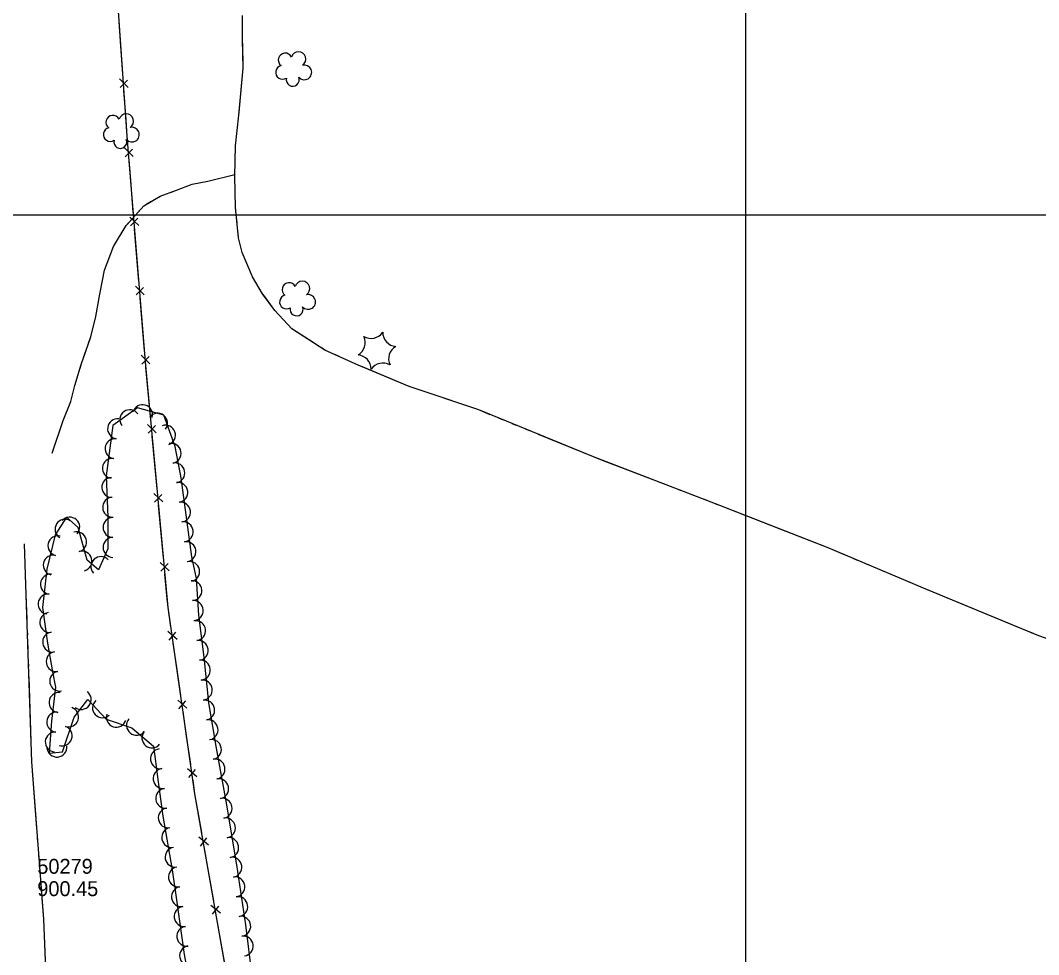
# Model space of a CAD drawing. Extents: x 353423 to 364002, y 127000 to 201942.
# Drawn here: x 361707.9 to 362117.9, y 131702.2 to 132078.2 of the extents above; entities that cross this region are included whole.
import ezdxf

# ---------------------------------------------------------------- set-up
doc = ezdxf.new("R2010")
doc.units = 0
for name, color, linetype in [('E_DTM_SlopeBottom', 7, 'Continuous'), ('E_FEN_Generic', 7, 'Continuous'), ('E_LAND_TreeLine', 7, 'Continuous'), ('E_RDWY_AsphConc', 7, 'Continuous'), ('E_STRUCT_WingWall', 7, 'Continuous')]:
    doc.layers.add(name, color=color, linetype=linetype)

msp = doc.modelspace()

# ---------------------------------------------------------------- linework, layer by layer
at = {"layer": 'E_DTM_SlopeBottom'}
for p, q in [((361751.3, 132051.27), (361747.8, 132054.76)), ((361748.05, 132051.22), (361751.02, 132054.23)), ((361753.32, 132023.46), (361749.79, 132026.91)), ((361750.08, 132023.37), (361753.02, 132026.42)), ((361755.58, 131995.64), (361752.04, 131999.09)), ((361752.33, 131995.55), (361755.27, 131998.6)), ((361757.83, 131967.83), (361754.3, 131971.28)), ((361754.58, 131967.74), (361757.52, 131970.78)), ((361760.08, 131940.01), (361756.55, 131943.46)), ((361756.84, 131939.92), (361759.78, 131942.97)), ((361762.66, 131912.24), (361759.08, 131915.65)), ((361759.41, 131912.11), (361762.32, 131915.2)), ((361765.22, 131884.45), (361761.65, 131887.86)), ((361761.97, 131884.33), (361764.88, 131887.41)), ((361767.78, 131856.67), (361764.21, 131860.08)), ((361764.54, 131856.54), (361767.44, 131859.62)), ((361771.02, 131829.05), (361767.27, 131832.27)), ((361767.78, 131828.75), (361770.52, 131831.98)), ((361775.01, 131801.43), (361771.26, 131804.65)), ((361771.77, 131801.13), (361774.51, 131804.36)), ((361779, 131773.81), (361775.25, 131777.03)), ((361775.76, 131773.51), (361778.5, 131776.74)), ((361783.62, 131746.34), (361779.78, 131749.45)), ((361780.4, 131745.95), (361783.04, 131749.26)), ((361788.47, 131718.86), (361784.63, 131721.96)), ((361785.24, 131718.46), (361787.88, 131721.77))]:
    msp.add_line(p, q, dxfattribs=at)
for points in [[(361878.29, 131213.33), (361848.45, 131372.9), (361823.99, 131512.17), (361810.41, 131584.23), (361778.23, 131766.92), (361767.39, 131841.96), (361758.28, 131940.75), (361750.91, 132031.6), (361745.14, 132114.91), (361734.25, 132261.02), (361730.83, 132314.1), (361722.15, 132402.74), (361735.2, 132462.79), (361756.62, 132560.57), (361777.4, 132659.3), (361799.83, 132762.09), (361820.91, 132859.48), (361836.68, 132931.42), (361851.79, 133001.8)], [(361748.4, 132067.88), (361747.71, 132077.83)], [(361749.18, 132056.57), (361748.4, 132067.88)], [(361750.33, 132040.04), (361749.64, 132049.99)], [(361751.15, 132028.73), (361750.91, 132031.6), (361750.33, 132040.04)], [(361752.49, 132012.22), (361751.68, 132022.16)], [(361753.4, 132000.92), (361752.49, 132012.22)], [(361754.74, 131984.4), (361753.93, 131994.34)], [(361755.66, 131973.1), (361754.74, 131984.4)], [(361756.99, 131956.59), (361756.19, 131966.53)], [(361757.91, 131945.29), (361756.99, 131956.59)], [(361759.38, 131928.78), (361758.47, 131938.71)], [(361760.42, 131917.49), (361759.38, 131928.78)], [(361761.94, 131900.99), (361761.03, 131910.93)], [(361762.98, 131889.7), (361761.94, 131900.99)], [(361764.51, 131873.21), (361763.59, 131883.14)], [(361765.55, 131861.91), (361764.51, 131873.21)], [(361767.07, 131845.42), (361766.15, 131855.35)], [(361768.51, 131834.17), (361767.39, 131841.96), (361767.07, 131845.42)], [(361770.88, 131817.78), (361769.46, 131827.65)], [(361772.51, 131806.55), (361770.88, 131817.78)], [(361774.87, 131790.16), (361773.45, 131800.03)], [(361776.5, 131778.93), (361774.87, 131790.16)], [(361779, 131762.56), (361778.23, 131766.92), (361777.44, 131772.41)], [(361780.97, 131751.39), (361779, 131762.56)], [(361783.84, 131735.07), (361782.11, 131744.9)], [(361785.81, 131723.91), (361783.84, 131735.07)], [(361788.68, 131707.59), (361786.95, 131717.41)], [(361790.65, 131696.42), (361788.68, 131707.59)]]:
    msp.add_lwpolyline(points, dxfattribs=at)
at = {"layer": 'E_FEN_Generic'}
msp.add_lwpolyline([(361801.32, 131693.58), (361798.69, 131714.25), (361795.08, 131738.38), (361790.81, 131764), (361786.89, 131785.27), (361783.78, 131803.52), (361781.99, 131822.01), (361779.78, 131838.92), (361778.8, 131853.62), (361777.01, 131862.31), (361772.64, 131894.17), (361770.24, 131906.73), (361765.7, 131919.32), (361755.11, 131922.31), (361745.13, 131915.21), (361742.44, 131894.89), (361743.14, 131878.24), (361743.11, 131865.58), (361739.45, 131857.09), (361734.77, 131861.05), (361731.16, 131874.14), (361726.45, 131878.26), (361721.96, 131871.15), (361718.6, 131857.31), (361716.78, 131841.89), (361718.86, 131827.57), (361720.92, 131816.11), (361722.08, 131809.89), (361720.46, 131796.22), (361719.53, 131783.3), (361724.84, 131783.88), (361729.53, 131797.8), (361735.06, 131804.86), (361742.41, 131796.96), (361752.74, 131793.45), (361761.55, 131786.17), (361763.33, 131772.74), (361765.22, 131757.98), (361769.01, 131736.32), (361770.84, 131724.31), (361773.81, 131702.33), (361778.15, 131679.04)], dxfattribs=at)
for centre, radius, start, end in [((361819.91, 132062.67), 2.97, 302.955, 164.1889), ((361814.55, 132062.27), 2.78, 25.9259, 233.6989), ((361813.51, 132057.31), 2.78, 102.6029, 303.614), ((361822.24, 132057.3), 2.97, 220.6058, 103.5791), ((361817.58, 132054.33), 2.61, 165.311, 23.2437), ((361745.16, 132037.24), 2.78, 25.9259, 233.6989), ((361750.52, 132037.64), 2.97, 302.955, 164.1889), ((361744.12, 132032.28), 2.78, 102.6029, 303.614), ((361752.85, 132032.27), 2.97, 220.6058, 103.5791), ((361748.19, 132029.3), 2.61, 165.311, 23.2437), ((361816.11, 131969.87), 2.78, 25.9259, 233.6989), ((361821.47, 131970.27), 2.97, 302.955, 164.1889), ((361815.07, 131964.91), 2.78, 102.6029, 303.614), ((361823.8, 131964.9), 2.97, 220.6058, 103.5791), ((361819.14, 131961.93), 2.61, 165.311, 23.2437), ((361841.03, 131948.55), 5.72, 299.7427, 25.5076), ((361849.08, 131955.96), 5.72, 239.7427, 325.5076), ((361859.52, 131952.7), 5.72, 179.7427, 265.5076), ((361861.91, 131942.02), 5.72, 119.7427, 205.5076), ((361843.42, 131937.88), 5.72, 359.7427, 85.5076), ((361853.86, 131934.61), 5.72, 59.7427, 145.5076), ((361757.14, 131919.56), 4.01, 344.234, 164.2187), ((361751.99, 131917.51), 4.01, 35.4383, 215.4229), ((361763.18, 131916.11), 4.01, 322.1229, 142.1076), ((361747.07, 131913.84), 4.01, 82.4731, 262.4577), ((361766.35, 131911.32), 4.01, 289.8486, 109.8332), ((361746.02, 131905.88), 4.01, 82.4731, 262.4577), ((361768.63, 131903.99), 4.01, 280.8201, 100.8047), ((361744.96, 131897.93), 4.01, 82.4731, 262.4577), ((361770.13, 131896.11), 4.01, 280.8201, 100.8047), ((361744.74, 131890.29), 4.01, 92.3905, 272.3751), ((361771.33, 131888.28), 4.01, 277.8188, 97.8035), ((361745.07, 131882.27), 4.01, 92.3905, 272.3751), ((361772.42, 131880.33), 4.01, 277.8188, 97.8035), ((361725.9, 131873.45), 4.01, 57.7381, 237.7228), ((361727.82, 131874.27), 4.01, 318.7959, 138.7806), ((361745.23, 131874.16), 4.01, 89.899, 269.8837), ((361773.51, 131872.38), 4.01, 277.8188, 97.8035), ((361723.06, 131866.79), 4.01, 76.3618, 256.3465), ((361730.58, 131868.35), 4.01, 285.4127, 105.3974), ((361745.21, 131866.13), 4.01, 89.899, 269.8837), ((361774.6, 131864.43), 4.01, 277.8188, 97.8035), ((361721.17, 131858.99), 4.01, 76.3618, 256.3465), ((361732.71, 131860.61), 4.01, 285.4127, 105.3974), ((361740.33, 131858.4), 4.01, 42.072, 222.0567), ((361776.08, 131856.4), 4.01, 281.5976, 101.5822), ((361720.01, 131851.31), 4.01, 83.2679, 263.2526), ((361777.02, 131848.73), 4.01, 273.844, 93.8287), ((361719.06, 131843.34), 4.01, 83.2679, 263.2526), ((361777.56, 131840.72), 4.01, 273.844, 93.8287), ((361719.76, 131835.94), 4.01, 98.2688, 278.2535), ((361778.49, 131832.62), 4.01, 277.4507, 97.4353), ((361720.92, 131828), 4.01, 98.2688, 278.2535), ((361779.53, 131824.66), 4.01, 277.4507, 97.4353), ((361722.33, 131820.17), 4.01, 100.2417, 280.2263), ((361780.39, 131816.75), 4.01, 275.5252, 95.5099), ((361723.77, 131812.28), 4.01, 100.4909, 280.4756), ((361781.16, 131808.76), 4.01, 275.5252, 95.5099), ((361723.46, 131803.7), 4.01, 83.2606, 263.2453), ((361732.44, 131804.91), 4.01, 231.9573, 51.942), ((361740.99, 131801.57), 4.01, 132.9396, 312.9243), ((361782.14, 131800.65), 4.01, 279.6883, 99.673), ((361722.54, 131795.82), 4.01, 85.8786, 265.8632), ((361727.34, 131797.87), 4.01, 251.374, 71.3587), ((361746.58, 131797.76), 4.01, 161.2371, 341.2218), ((361754.7, 131794.55), 4.01, 140.453, 320.4377), ((361783.49, 131792.74), 4.01, 279.6883, 99.673), ((361721.96, 131787.82), 4.01, 85.8786, 265.8632), ((361724.77, 131790.26), 4.01, 251.374, 71.3587), ((361760.89, 131789.44), 4.01, 140.453, 320.4377), ((361784.84, 131784.8), 4.01, 280.4449, 100.4296), ((361722.62, 131785.75), 4.01, 186.2875, 6.2722), ((361764.35, 131781.06), 4.01, 97.5498, 277.5344), ((361786.3, 131776.9), 4.01, 280.4449, 100.4296), ((361765.4, 131773.11), 4.01, 97.5498, 277.5344), ((361787.75, 131769.01), 4.01, 280.4449, 100.4296), ((361766.42, 131765.14), 4.01, 97.3089, 277.2936), ((361789.15, 131761.14), 4.01, 279.4776, 99.4623), ((361767.48, 131757.28), 4.01, 99.9186, 279.9032), ((361790.48, 131753.22), 4.01, 279.4776, 99.4623), ((361768.86, 131749.37), 4.01, 99.9186, 279.9032), ((361791.8, 131745.31), 4.01, 279.4776, 99.4623), ((361770.24, 131741.46), 4.01, 99.9186, 279.9032), ((361793.1, 131737.42), 4.01, 278.5101, 98.4948), ((361771.56, 131733.5), 4.01, 98.6671, 278.6518), ((361772.77, 131725.56), 4.01, 98.6671, 278.6518), ((361794.29, 131729.48), 4.01, 278.5101, 98.4948), ((361795.47, 131721.55), 4.01, 278.5101, 98.4948), ((361773.87, 131717.58), 4.01, 97.7051, 277.6898), ((361796.65, 131713.65), 4.01, 277.2664, 97.251), ((361774.94, 131709.62), 4.01, 97.7051, 277.6898), ((361797.66, 131705.69), 4.01, 277.2664, 97.251), ((361776.05, 131701.78), 4.01, 100.5738, 280.5585)]:
    msp.add_arc(centre, radius, start, end, dxfattribs=at)
at = {"layer": 'E_LAND_TreeLine'}
for p, q in [((362000, 131000), (362000, 133500)), ((360000, 132000), (364000, 132000))]:
    msp.add_line(p, q, dxfattribs=at)
at = {"layer": 'E_STRUCT_WingWall'}
for points in [[(362185.3, 131805.89), (362117.34, 131830.79), (362071.58, 131849.73), (362033.1, 131865.92), (361989.5, 131882.99), (361938.65, 131902.56), (361892.46, 131921.43), (361864.41, 131930.88), (361843.91, 131939.48), (361830.52, 131945.55), (361817.16, 131954.14), (361810.38, 131961.47), (361805.48, 131968.24), (361801.35, 131975.07), (361797.17, 131984.77), (361795.76, 131990.67), (361794.61, 132002.91), (361794.22, 132015.51), (361794.55, 132027.73), (361795.94, 132040.05), (361797.6, 132058.99), (361797.42, 132070.57), (361797.39, 132080.18)], [(361797.41, 132072.9), (361797.41, 132074.82)], [(361796.05, 132041.33), (361797.6, 132058.99), (361797.44, 132069.07)], [(361794.28, 132013.62), (361794.22, 132015.51), (361794.55, 132027.73), (361795.94, 132040.05), (361796.05, 132041.33)], [(361720.71, 131903.99), (361725.2, 131917.22), (361728.24, 131924.91), (361729.92, 131931.3), (361732.47, 131939.8), (361736.33, 131950.91), (361738.27, 131959.02), (361739.92, 131968.03), (361741.82, 131977.72), (361745.36, 131987.18), (361750.49, 131995.66), (361757.6, 132003.6), (361764.25, 132007.49), (361770.84, 132009.92), (361777.08, 132012.3), (361783.38, 132013.47), (361794.24, 132016.22)], [(361768.73, 132009.15), (361770.84, 132009.92), (361777.08, 132012.3), (361783.38, 132013.47), (361794.24, 132016.22)], [(361794.46, 132007.87), (361794.4, 132009.79)], [(361758.89, 132004.35), (361760.47, 132005.28)], [(361763.63, 132007.13), (361764.25, 132007.49), (361765.29, 132007.88)], [(361754.93, 132000.61), (361756.15, 132001.98)], [(361794.68, 132002.13), (361794.61, 132002.91), (361794.58, 132004.04)], [(361741.13, 131974.21), (361741.82, 131977.72), (361745.36, 131987.18), (361750.49, 131995.66), (361752.48, 131997.88)], [(361795.22, 131996.4), (361795.04, 131998.31)], [(361806.22, 131967.21), (361805.48, 131968.24), (361801.35, 131975.07), (361797.17, 131984.77), (361795.76, 131990.67), (361795.58, 131992.58)], [(361735.41, 131948.28), (361736.33, 131950.91), (361738.27, 131959.02), (361739.92, 131968.03), (361741.13, 131974.21)], [(361826.18, 131948.34), (361817.16, 131954.14), (361810.38, 131961.47), (361806.22, 131967.21)], [(361733.61, 131943.09), (361734.21, 131944.82)], [(361831.06, 131945.31), (361830.52, 131945.55), (361829.41, 131946.27)], [(361836.29, 131942.93), (361834.55, 131943.73)], [(361731.89, 131937.87), (361732.42, 131939.62)], [(361841.53, 131940.56), (361839.78, 131941.35)], [(361870.84, 131928.71), (361864.41, 131930.88), (361845.03, 131939.01)], [(361730.31, 131932.6), (361730.84, 131934.36)], [(361720.71, 131903.99), (361725.2, 131917.22), (361728.24, 131924.91), (361729.34, 131929.08)], [(361897.08, 131919.54), (361892.46, 131921.43), (361870.84, 131928.71)], [(361902.4, 131917.37), (361900.63, 131918.09)], [(361907.73, 131915.2), (361905.95, 131915.92)], [(361913.05, 131913.02), (361911.28, 131913.74)], [(361942.36, 131901.14), (361938.65, 131902.56), (361916.6, 131911.57)], [(361968.31, 131891.15), (361942.36, 131901.14)], [(361973.68, 131889.08), (361971.89, 131889.77)], [(361979.04, 131887.02), (361977.26, 131887.71)], [(361984.41, 131884.95), (361982.62, 131885.64)], [(362013.88, 131873.44), (361989.5, 131882.99), (361987.99, 131883.57)], [(362039.7, 131863.14), (362033.1, 131865.92), (362013.88, 131873.44)], [(361755.35, 131196.84), (361746.04, 131295.32), (361742.36, 131350.07), (361737.57, 131416.58), (361731.88, 131476.62), (361728.1, 131525.36), (361724.43, 131579.07), (361720.25, 131646.96), (361717.32, 131716.49), (361712.56, 131779.84), (361710.33, 131846.97), (361709.6, 131867.55)], [(361710.66, 131837.1), (361710.33, 131846.97), (361709.6, 131867.55)], [(362045, 131860.91), (362043.23, 131861.65)], [(362050.3, 131858.68), (362048.54, 131859.42)], [(362055.61, 131856.45), (362053.84, 131857.19)], [(362084.79, 131844.26), (362071.58, 131849.73), (362059.14, 131854.96)], [(362110.48, 131833.63), (362084.79, 131844.26)], [(361710.87, 131830.8), (361710.8, 131832.9)], [(362115.79, 131831.43), (362114.02, 131832.16)], [(361711.08, 131824.5), (361711.01, 131826.6)], [(361711.29, 131818.2), (361711.22, 131820.3)], [(361712.44, 131783.55), (361711.43, 131814)], [(361714.57, 131753.16), (361712.56, 131779.84), (361712.44, 131783.55)], [(361715.04, 131746.87), (361714.88, 131748.97)], [(361715.51, 131740.59), (361715.35, 131742.68)], [(361715.98, 131734.3), (361715.83, 131736.39)], [(361718.03, 131699.7), (361717.32, 131716.49), (361716.3, 131730.11)]]:
    msp.add_lwpolyline(points, dxfattribs=at)

# ---------------------------------------------------------------- texts
at = {"layer": 'E_RDWY_AsphConc'}
for s, p in [('50279', (361714.75, 131734.78)), ('50279', (361714.75, 131734.78)), ('900.45', (361714.75, 131725.78)), ('900.45', (361714.75, 131725.78))]:
    msp.add_text(s, height=6, dxfattribs=at).set_placement(p)

doc.saveas('drawing.dxf')
